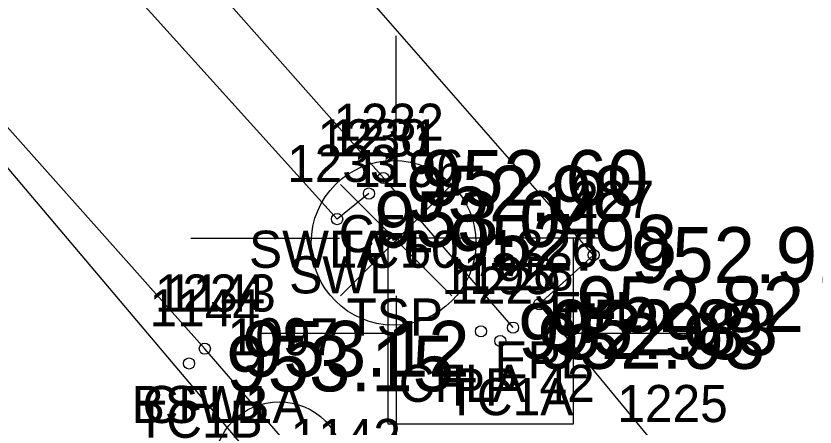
# Model space of a CAD drawing. Extents: x 1575382 to 1578175, y 1099175 to 1101955.
# Drawn here: x 1576370.61 to 1576392.13, y 1099612.15 to 1099623.22 of the extents above; entities that cross this region are included whole.
import ezdxf

# ---------------------------------------------------------------- set-up
doc = ezdxf.new("R2010")
doc.units = 0
for name, color, linetype in [('RD_EX_Conc', 7, 'Continuous'), ('RD_EX_Conc_txCode', 7, 'Continuous'), ('RD_EX_DR_Pipe', 7, 'Continuous'), ('RD_EX_DV_Prop_txCode', 7, 'Continuous'), ('RD_EX_DV_PropPin', 7, 'Continuous'), ('RD_EX_Road', 7, 'Continuous'), ('RD_EX_Road_txCode', 7, 'Continuous'), ('RD_EX_SU_Pole', 7, 'Continuous'), ('RD_EX_TX_Conc_ELEV', 7, 'Continuous'), ('RD_EX_TX_Road_ELEV', 7, 'Continuous'), ('RD_EX_TX_UT_ELEV', 7, 'Continuous'), ('RD_EX_UT', 7, 'Continuous'), ('RD_EX_UT_txCode', 7, 'Continuous'), ('RD_HC_Data', 7, 'Continuous'), ('RD_HC_Survey_ELEV', 7, 'Continuous'), ('RD_SMD_Locator', 7, 'Continuous')]:
    doc.layers.add(name, color=color, linetype=linetype)

msp = doc.modelspace()

# ---------------------------------------------------------------- linework, layer by layer
at = {"layer": 'RD_EX_Conc'}
for points in [[(1576375.693, 1099614.257), (1576362.913, 1099628.604), (1576326.832, 1099655.211), (1576295.504, 1099672.667), (1576283.882, 1099680.167), (1576241.839, 1099705.437), (1576196.963, 1099731.776)], [(1576380.113, 1099618.436), (1576379.256, 1099617.747), (1576366.663, 1099631.694), (1576329.188, 1099659.093), (1576302.247, 1099675.096), (1576304.479, 1099678.037)], [(1576383.996, 1099614.827), (1576380.504, 1099618.856), (1576368.095, 1099632.864), (1576355.6, 1099645.123), (1576345.065, 1099653.901), (1576337.296, 1099659.108)], [(1576360.945, 1099591.467), (1576368.12, 1099597.926), (1576371.825, 1099601.361), (1576376.294, 1099605.493), (1576378.653, 1099607.482), (1576379.425, 1099608.864), (1576379.064, 1099610.368), (1576375.693, 1099614.257)]]:
    msp.add_lwpolyline(points, dxfattribs=at)
at = {"layer": 'RD_EX_DR_Pipe'}
msp.add_lwpolyline([(1576364.841, 1099525.95), (1576408.84, 1099579.579), (1576408.84, 1099579.579), (1576384.131, 1099602.876), (1576384.131, 1099602.876), (1576335.971, 1099659.822), (1576335.971, 1099659.822), (1576168.711, 1099756.104)], dxfattribs=at)
at = {"layer": 'RD_EX_DV_PropPin'}
msp.add_circle((1576377.695, 1099611.08), 1.75, dxfattribs=at)
at = {"layer": 'RD_EX_Road'}
msp.add_lwpolyline([(1576385.974, 1099603.197), (1576388.618, 1099605.879), (1576388.149, 1099611.282), (1576384.699, 1099615.456), (1576386.165, 1099616.781), (1576370.202, 1099635.027), (1576357.376, 1099647.313), (1576346.631, 1099656.319), (1576334.076, 1099664.489), (1576324.149, 1099670.375), (1576289.725, 1099690.815), (1576247.005, 1099716.046), (1576203.005, 1099742.272)], dxfattribs=at)
at = {"layer": 'RD_EX_SU_Pole'}
for p, q in [((1576380.845, 1099618.679), (1576380.845, 1099622.679)), ((1576382.345, 1099618.679), (1576379.345, 1099615.679)), ((1576379.345, 1099618.679), (1576382.345, 1099615.679)), ((1576379.32, 1099617.227), (1576375.32, 1099617.227)), ((1576382.359, 1099617.244), (1576386.375, 1099617.244)), ((1576380.845, 1099615.679), (1576380.845, 1099611.679))]:
    msp.add_line(p, q, dxfattribs=at)
msp.add_circle((1576380.777, 1099617.111), 2.217, dxfattribs=at)
at = {"layer": 'RD_EX_UT'}
for p, q in [((1576385.621, 1099617.236), (1576380.621, 1099617.236)), ((1576380.621, 1099617.236), (1576380.621, 1099612.236)), ((1576385.621, 1099612.236), (1576385.621, 1099617.236)), ((1576377.19, 1099614.674), (1576380.659, 1099614.674)), ((1576385.549, 1099614.674), (1576389.19, 1099614.674)), ((1576380.621, 1099612.236), (1576385.621, 1099612.236))]:
    msp.add_line(p, q, dxfattribs=at)
at = {"layer": 'RD_SMD_Locator'}
for centre in [(1576380.504, 1099618.856), (1576380.113, 1099618.436), (1576380.113, 1099618.436), (1576379.256, 1099617.747), (1576380.777, 1099617.111), (1576386.165, 1099616.781), (1576384.699, 1099615.456), (1576383.13, 1099614.727), (1576383.996, 1099614.827), (1576383.65, 1099614.467), (1576375.693, 1099614.257), (1576375.693, 1099614.257), (1576375.269, 1099613.86)]:
    msp.add_circle(centre, 0.15, dxfattribs=at)

# ---------------------------------------------------------------- texts
at = {"layer": 'RD_EX_Conc_txCode'}
for s, p in [('1232', (1576379.158, 1099619.856)), ('1230', (1576378.727, 1099619.436)), ('1231', (1576379.05, 1099619.436)), ('1233', (1576377.909, 1099618.747)), ('CFL', (1576379.299, 1099616.856)), ('SWLA 60', (1576376.884, 1099616.436)), ('TC1', (1576379.152, 1099616.436)), ('SWL', (1576377.964, 1099615.747)), ('1228', (1576382.649, 1099615.827)), ('1229', (1576382.304, 1099615.467)), ('1234', (1576374.347, 1099615.257)), ('1143', (1576374.63, 1099615.257)), ('1144', (1576374.206, 1099614.86)), ('CFLA 42', (1576380.917, 1099612.827)), ('TC1A', (1576382.202, 1099612.467)), ('BSW1A', (1576373.725, 1099612.257)), ('CFLB', (1576374.016, 1099612.257)), ('TC1B', (1576373.836, 1099611.86)), ('1142', (1576378.001, 1099611.368))]:
    msp.add_text(s, height=1, dxfattribs=at).set_placement(p)
at = {"layer": 'RD_EX_DV_Prop_txCode'}
msp.add_text('1097', height=1, dxfattribs=at).set_placement((1576376.309, 1099614.08))
at = {"layer": 'RD_EX_Road_txCode'}
for s, p in [('1227', (1576384.819, 1099617.781)), ('1226', (1576383.329, 1099616.456)), ('EPL', (1576384.961, 1099614.781)), ('EPL', (1576383.494, 1099613.456)), ('1225', (1576386.803, 1099612.282))]:
    msp.add_text(s, height=1, dxfattribs=at).set_placement(p)
at = {"layer": 'RD_EX_TX_Conc_ELEV'}
for s, p in [('952.60', (1576381.504, 1099618.106)), ('952.98', (1576381.113, 1099617.686)), ('952.98', (1576381.113, 1099617.686)), ('953.04', (1576380.256, 1099616.997)), ('952.83', (1576384.996, 1099614.077)), ('952.93', (1576384.65, 1099613.717)), ('953.12', (1576376.693, 1099613.507)), ('953.12', (1576376.693, 1099613.507)), ('953.15', (1576376.269, 1099613.11))]:
    msp.add_text(s, height=1.5, dxfattribs=at).set_placement(p)
at = {"layer": 'RD_EX_TX_Road_ELEV'}
for s, p in [('952.91', (1576387.165, 1099616.031)), ('952.82', (1576385.699, 1099614.706))]:
    msp.add_text(s, height=1.5, dxfattribs=at).set_placement(p)
at = {"layer": 'RD_EX_TX_UT_ELEV'}
msp.add_text('952.98', height=1.5, dxfattribs=at).set_placement((1576382.277, 1099616.361))
at = {"layer": 'RD_EX_UT_txCode'}
for s, p in [('1196', (1576379.69, 1099618.611)), ('1195', (1576382.067, 1099615.727)), ('TSP', (1576379.509, 1099614.611)), ('PP', (1576382.35, 1099612.727))]:
    msp.add_text(s, height=1, dxfattribs=at).set_placement(p)
at = {"layer": 'RD_HC_Data'}
msp.add_text('S 39%%d 37\' 44" E', height=6, rotation=309.6289, dxfattribs=at).set_placement((1576380.227, 1099642.779))
at = {"layer": 'RD_HC_Survey_ELEV'}
msp.add_text('952.93', height=1.5, dxfattribs=at).set_placement((1576384.13, 1099613.977))

doc.saveas('drawing.dxf')
